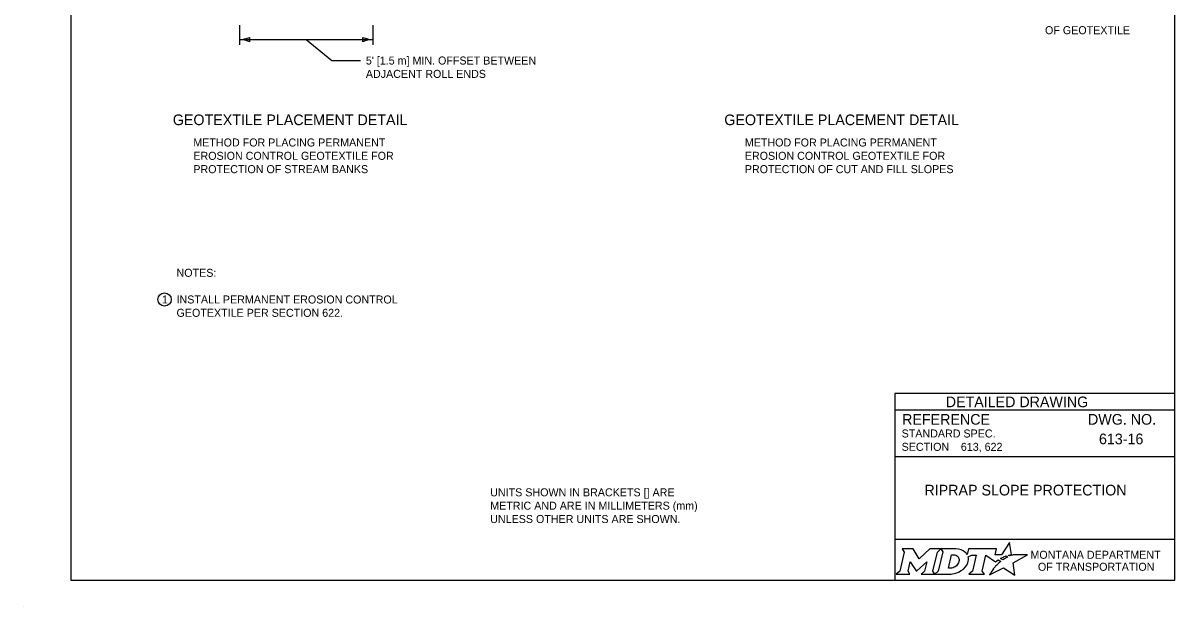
# Model space of a CAD drawing. Extents: x 49991.4 to 50021, y 49987.6 to 50011.4.
# Drawn here: x 49999.98 to 50008.61, y 49999.86 to 50004.24 of the extents above; entities that cross this region are included whole.
import ezdxf

# ---------------------------------------------------------------- set-up
doc = ezdxf.new("R2010")
doc.units = 0
for name, color, linetype in [('Level 1', 7, 'Continuous'), ('Level 2', 7, 'Continuous'), ('Level 3', 7, 'Continuous')]:
    doc.layers.add(name, color=color, linetype=linetype)

msp = doc.modelspace()

# ---------------------------------------------------------------- linework, layer by layer
at = {"layer": 'Level 1'}
msp.add_line((49999.9766, 49999.8624), (49999.9766, 49999.8624), dxfattribs=at)
msp.add_lwpolyline([(50008.6146, 50011.2628), (50000.3356, 50011.2628), (50000.3356, 50000.0624), (50008.6146, 50000.0624)], close=True, dxfattribs=at)
at = {"layer": 'Level 2'}
for p, q in [((50008.6146, 50001.4624), (50006.5146, 50001.4624)), ((50006.5146, 50001.4624), (50006.5146, 50000.0624)), ((50008.6146, 50001.3374), (50006.5146, 50001.3374)), ((50008.2507, 50001.1223), (50008.2507, 50001.1223)), ((50008.6146, 50000.9874), (50006.5146, 50000.9874)), ((50007.0089, 50001.0629), (50007.0089, 50001.0629)), ((50007.5646, 50000.7383), (50007.5646, 50000.7383)), ((50008.6146, 50000.3693), (50006.5146, 50000.3693))]:
    msp.add_line(p, q, dxfattribs=at)
for points in [[(50006.5701, 50000.2974), (50006.5842, 50000.274), (50006.5507, 50000.1307), (50006.525, 50000.1082), (50006.6266, 50000.1082), (50006.6131, 50000.131), (50006.6293, 50000.2011), (50006.673, 50000.1321), (50006.6783, 50000.1321), (50006.7534, 50000.2016), (50006.737, 50000.1305), (50006.7123, 50000.1085), (50006.8139, 50000.1085), (50006.8001, 50000.1318), (50006.8333, 50000.2742)], [(50006.8333, 50000.2742), (50006.8586, 50000.2974), (50006.7762, 50000.2974), (50006.6966, 50000.2244), (50006.6521, 50000.2971), (50006.5701, 50000.2974)], [(50006.9722, 50000.2974), (50006.8586, 50000.2974), (50006.8733, 50000.2745), (50006.8394, 50000.1307), (50006.8139, 50000.1085), (50006.9245, 50000.1085)], [(50007.3771, 50000.2447), (50007.3668, 50000.2503), (50007.3784, 50000.2531), (50007.39, 50000.2551), (50007.3726, 50000.3452), (50007.3131, 50000.2539), (50007.2658, 50000.2532), (50007.2761, 50000.2973), (50007.0669, 50000.2974), (50007.0568, 50000.2549), (50007.051, 50000.2632)], [(50006.9962, 50000.2107), (50006.995, 50000.2026), (50006.9918, 50000.1933), (50006.9876, 50000.1851), (50006.982, 50000.1776), (50006.9755, 50000.1707), (50006.9676, 50000.1644), (50006.9593, 50000.1597), (50006.9502, 50000.1558), (50006.9411, 50000.1535), (50006.9319, 50000.1526), (50006.916, 50000.1526), (50006.9396, 50000.2526), (50006.9556, 50000.2526), (50006.9632, 50000.252), (50006.9708, 50000.2501), (50006.9774, 50000.2471), (50006.9835, 50000.2429), (50006.9883, 50000.2379), (50006.992, 50000.2319), (50006.9947, 50000.2257), (50006.9963, 50000.2183), (50006.9963, 50000.2153), (50006.9962, 50000.2107)], [(50007.0636, 50000.2383), (50007.0882, 50000.2514), (50007.1251, 50000.2514), (50007.0965, 50000.1309), (50007.069, 50000.1082), (50007.1852, 50000.1082), (50007.1682, 50000.1311), (50007.1964, 50000.2513), (50007.2677, 50000.1996), (50007.2888, 50000.2147), (50007.3085, 50000.2038)], [(50007.2527, 50000.1479), (50007.2374, 50000.1235), (50007.2327, 50000.116), (50007.2269, 50000.1074), (50007.2246, 50000.1031), (50007.3299, 50000.1562), (50007.4138, 50000.1011), (50007.4007, 50000.1938), (50007.5076, 50000.2522), (50007.4583, 50000.253), (50007.4282, 50000.2534), (50007.4074, 50000.2537), (50007.4006, 50000.2522), (50007.3957, 50000.251), (50007.3873, 50000.2487), (50007.3771, 50000.2447)], [(50007.3267, 50000.2171), (50007.3243, 50000.2154), (50007.306, 50000.225), (50007.3163, 50000.2307), (50007.3204, 50000.2329), (50007.329, 50000.2369), (50007.3347, 50000.2395), (50007.3426, 50000.2425), (50007.3499, 50000.2452), (50007.3617, 50000.2378), (50007.3577, 50000.2357), (50007.3531, 50000.2332), (50007.3489, 50000.231), (50007.3439, 50000.2281), (50007.342, 50000.227), (50007.3393, 50000.2254), (50007.3368, 50000.224), (50007.3345, 50000.2224), (50007.3319, 50000.2206), (50007.3292, 50000.2188), (50007.3267, 50000.2171)], [(50006.9702, 50000.1158), (50006.9786, 50000.1184), (50006.9916, 50000.1238), (50007.012, 50000.1348)], [(50007.2666, 50000.164), (50007.2666, 50000.164)]]:
    msp.add_lwpolyline(points, dxfattribs=at)
msp.add_circle((50001.0376, 50002.1677), 0.05, dxfattribs=at)
for centre, radius, start, end in [((50006.9953, 50000.219), 0.0709, 339.53292, 15.85821), ((50006.9513, 50000.2363), 0.1183, 300.91025, 339.13831)]:
    msp.add_arc(centre, radius, start, end, dxfattribs=at)
for centre, major_axis, ratio, start_param, end_param in [((50006.9701, 50000.25), (0.0834, -0.0037), 0.568097, 0.61298, 1.570796), ((50007.0257, 50000.2573), (0.0361, -0.0295), 0.469099, 1.225588, 1.570796), ((50007.2974, 50000.1941), (-0.0112, -0.0097), 0.021651, 3.157348, 6.283185), ((50006.9248, 50000.2568), (0, 0.1484), 0.987302, 3.139398, 3.456847), ((50007.2597, 50000.1559), (-0.00694, -0.00806), 0.008222, 0, 3.137361), ((50007.2764, 50000.1742), (-0.0098, -0.0102), 0.016458, 3.141593, 6.279097)]:
    msp.add_ellipse(centre, major_axis=major_axis, ratio=ratio, start_param=start_param, end_param=end_param, dxfattribs=at)
at = {"layer": 'Level 3'}
for p, q in [((50001.5997, 50004.2248), (50001.5997, 50004.0763)), ((50002.5997, 50004.2248), (50002.5997, 50004.0763)), ((50001.5997, 50004.1163), (50002.5997, 50004.1163)), ((50002.0997, 50004.1163), (50002.2932, 50003.9592)), ((50002.2932, 50003.9592), (50002.5073, 50003.9592))]:
    msp.add_line(p, q, dxfattribs=at)
for centre, radius, start, end in [((50001.5882, 50004.349), 0.233, 272.82731, 292.07716), ((50001.5905, 50003.8941), 0.2223, 67.45601, 87.63952), ((50001.7279, 50004.1163), 0.0548, 162.13882, 197.86118), ((50002.6088, 50004.3384), 0.2223, 247.45601, 267.63952), ((50002.4715, 50004.1163), 0.0548, 342.13882, 17.86118), ((50002.6112, 50003.8836), 0.233, 92.82731, 112.07716)]:
    msp.add_arc(centre, radius, start, end, dxfattribs=at)

# ---------------------------------------------------------------- texts
at = {"layer": 'Level 2'}
for s, height, p in [('OF GEOTEXTILE', 0.06, (50007.6403, 50004.1567)), ("5' [1.5 m] MIN. OFFSET BETWEEN", 0.06, (50002.5473, 50003.9292)), ('ADJACENT ROLL ENDS', 0.06, (50002.5473, 50003.8292)), ('GEOTEXTILE PLACEMENT DETAIL', 0.08, (50001.0997, 50003.4748)), ('GEOTEXTILE PLACEMENT DETAIL', 0.08, (50005.2352, 50003.4748)), ('METHOD FOR PLACING PERMANENT ', 0.06, (50001.2537, 50003.3148)), ('METHOD FOR PLACING PERMANENT ', 0.06, (50005.3891, 50003.3148)), ('EROSION CONTROL GEOTEXTILE FOR', 0.06, (50001.2537, 50003.2148)), ('EROSION CONTROL GEOTEXTILE FOR', 0.06, (50005.3891, 50003.2148)), ('PROTECTION OF STREAM BANKS', 0.06, (50001.2537, 50003.1148)), ('PROTECTION OF CUT AND FILL SLOPES', 0.06, (50005.3891, 50003.1148)), ('NOTES:', 0.06, (50001.1276, 50002.3377)), ('1', 0.06, (50001.0179, 50002.1377)), ('INSTALL PERMANENT EROSION CONTROL', 0.06, (50001.1276, 50002.1377)), ('GEOTEXTILE PER SECTION 622.', 0.06, (50001.1276, 50002.0377)), ('DETAILED DRAWING', 0.0799, (50006.8956, 50001.3599)), ('REFERENCE', 0.08, (50006.5682, 50001.229)), ('DWG. NO.', 0.08, (50007.9624, 50001.229)), ('STANDARD SPEC.', 0.06, (50006.5649, 50001.133)), ('613-16', 0.08, (50008.0448, 50001.0823)), ('SECTION', 0.06, (50006.5649, 50001.033)), ('613, 622', 0.06, (50007.0089, 50001.0329)), ('UNITS SHOWN IN BRACKETS [] ARE ', 0.06, (50003.4799, 50000.6917)), ('RIPRAP SLOPE PROTECTION', 0.08, (50006.7359, 50000.6983)), ('METRIC AND ARE IN MILLIMETERS (mm) ', 0.06, (50003.4799, 50000.5917)), ('UNLESS OTHER UNITS ARE SHOWN.', 0.06, (50003.4799, 50000.4917)), ('MONTANA DEPARTMENT', 0.06, (50007.5308, 50000.2236)), ('OF TRANSPORTATION', 0.06, (50007.587, 50000.1336))]:
    msp.add_text(s, height=height, dxfattribs=at).set_placement(p)

doc.saveas('drawing.dxf')
